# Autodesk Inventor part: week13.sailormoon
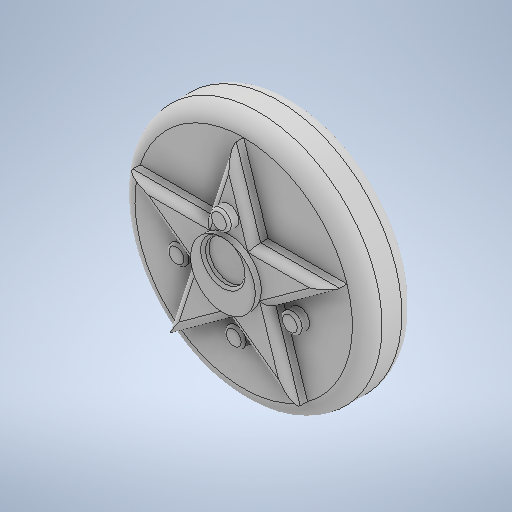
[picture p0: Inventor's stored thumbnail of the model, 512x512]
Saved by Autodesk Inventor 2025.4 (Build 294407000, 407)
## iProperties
Created: 2026-04
Part Number: week13.sailormoon
Material: Generic
Document SubType Name: Modeling
Designer: FLB013
Density: 1 g/cm^3
Appearance: Default
Author: FLB013
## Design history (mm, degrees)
sketch "Sketch1"
  geometry: C1 r 25 at (0, 0); 1 further point
  constraints: 1 centre point, 1 coincident
  dimensions: "d0" = 50 diameter of C1
extrude "Extrusion1" new body sketch "Sketch1" distance "d1" = 10; taper "d2" = 0 deg
fillet "Fillet1" dims "d3" = 3
sketch "Sketch2"
  geometry: L1 (0, 22)-(-4.939, 6.798); L2 (-7.992, -2.597)-(-12.931, -17.798); L3 (-20.923, 6.798)-(-4.939, 6.798); L4 (4.939, 6.798)-(20.923, 6.798); L5 (-20.923, 6.798)-(-7.992, -2.597); L6 (0, -8.403)-(12.931, -17.798); L7 (-12.931, -17.798)-(0, -8.403); L8 (7.992, -2.597)-(20.923, 6.798); L9 (12.931, -17.798)-(7.992, -2.597); L10 (4.939, 6.798)-(0, 22); A1 r 22 centre (0, 0) between (0, 22) and (-20.923, 6.798) reference; 3 further points
  constraints: 20 end point, 2 horizontal, 2 point on circle, 1 coincident, 6 other
extrude "Extrusion2" join sketch "Sketch2" distance "d4" = 3; taper "d5" = 0 deg
fillet "Fillet2" dims "d6" = 1.5
sketch "Sketch3"
  geometry: L1 (-3.849, 5.298)-(0, 17.146) reference; C1 r 4 at (0, 2.189); 2 further points
  constraints: 1 centre point, 1 coincident, 3 other
  dimensions: "d30" = 8 diameter of C1
extrude "Extrusion3" join sketch "Sketch3" distance "d7" = 1.2; taper "d8" = 0 deg
sketch "Sketch4"
  geometry: C1 r 2 at (0, 9.903); 1 further point
  constraints: 1 centre point
  dimensions: "d9" = 4 diameter of C1
sketch "Sketch5"
  geometry: C1 r 2 at (-11.608, -3.452); 1 further point
  constraints: 1 centre point
  dimensions: "d10" = 4 diameter of C1
sketch "Sketch6"
  geometry: C1 r 2 at (0, -12.064); 1 further point
  constraints: 1 centre point
  dimensions: "d11" = 4 diameter of C1
sketch "Sketch7"
  geometry: C1 r 2 at (11.349, -3.932); 1 further point
  constraints: 1 centre point
  dimensions: "d12" = 4 diameter of C1
extrude "Extrusion4" join sketch "Sketch6" distance "d13" = 2; taper "d14" = 0 deg
extrude "Extrusion5" join sketch "Sketch5" distance "d15" = 2; taper "d16" = 0 deg
extrude "Extrusion6" join sketch "Sketch7" distance "d17" = 2; taper "d18" = 0 deg
extrude "Extrusion7" join sketch "Sketch4" distance "d19" = 2; taper "d20" = 0 deg
fillet "Fillet3" dims "d21" = 0.5
fillet "Fillet4" dims "d22" = 0.5
fillet "Fillet5" dims "d23" = 0.5
fillet "Fillet6" dims "d24" = 0.5
fillet "Fillet7" dims "d25" = 0.5
body "Solid1"
